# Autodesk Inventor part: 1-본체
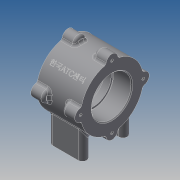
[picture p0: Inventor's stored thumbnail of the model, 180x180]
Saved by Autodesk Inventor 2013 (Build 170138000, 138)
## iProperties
Created: 2015-03
Part Number: 1-본체
Material: Generic
Document SubType Name: Modeling
Designer: kb
Density: 1 g/cm^3
Author: kb
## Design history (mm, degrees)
sketch "스케치1"
  geometry: L1 (-26, 37)-(26, 37); L2 (26, 37)-(26, 23.5); L3 (26, 23.5)-(4, 23.5); L4 (4, 23.5)-(4, 21); L5 (4, 21)-(-4, 21); L6 (-4, 21)-(-4, 23.5); L7 (-4, 23.5)-(-26, 23.5); L8 (-26, 23.5)-(-26, 37); L9 (-26, 0)-(26, 0); 2 further points
  constraints: 18 end point, 5 parallel, 3 perpendicular, 2 vertical alignment, 1 coincident, 1 horizontal, 1 midpoint
  dimensions: "d1" = 47 diameter of L7 L9; "d3" = 42 diameter of L5 L9; "d4" = 47 diameter of L3 L9; "d5" = 74 diameter of L1 L9; "d6" = 52 distance of L1.start L1.end; "d7" = 22 distance of L6.end L7.end; "d8" = 22 distance of L2.end L3.end
revolve "회전1" sketch "스케치1" stored, may be unused: angle "d9" = 90 deg
sketch "스케치2"
  geometry: L1 (0, 37)-(0, 0); C1 r 23.5 at (0, 0) reference; A1 r 37 centre (0, 0) between (0, 37) and (6.969, 36.338) reference; A2 r 7 centre (0, 37) between (6.969, 36.338) and (-6.969, 36.338); 1 further point
  constraints: 5 point on circle, 2 coincident, 2 end point, 1 centre point, 1 vertical
  dimensions: "d10" = 14 diameter of A2
extrude "돌출1" join sketch "스케치2" distance "d11" = 15; taper "d12" = 0 deg
hole "구멍1" sketch "스케치2" diameter "d13" = 3.242; stored, may be unused: countersink angle "d17" = 90 deg, drill point angle "d19" = 118 deg; dims "d14" = 8, "d15" = 4, "d16" = 2, "d18" = 11
node "작업 평면1"
node "작업 평면2"
sketch "스케치3"
  geometry: L1 (15, -24)-(-15, -24); L2 (-15, -24)-(-15, 24); L3 (-15, 24)-(15, 24); L4 (15, 24)-(15, -24); L5 (15, -24)-(-15, 24); L6 (-15, -24)-(15, 24); L7 (15, 29)-(-15, 29); L8 (15, 19)-(-15, 19); L9 (15, -19)-(-15, -19); L10 (15, -29)-(-15, -29); A1 r 5 centre (-15, 24) between (-15, 29) and (-15, 19); A2 r 5 centre (15, 24) between (15, 29) and (15, 19); A3 r 5 centre (-15, -24) between (-15, -19) and (-15, -29); A4 r 5 centre (15, -24) between (15, -19) and (15, -29); 1 further point
  constraints: 20 end point, 8 point on circle, 5 tangent, 4 centre point, 4 coincident, 3 point on line, 2 midpoint, 2 parallel, 1 horizontal, 1 perpendicular
  dimensions: "d24" = 48 distance of L3.end L1.start; "d26" = 30 distance of L2.end L3.end; "d27" = 10 diameter of A1; "d28" = 10 diameter of A2; "d29" = 10 diameter of A3; "d30" = 10 diameter of A4
extrude "돌출2" join sketch "스케치3" stored distance "d31" = 15; taper "d32" = 0 deg
sketch "스케치4"
  geometry: L1 (0, -37)-(-37, -37); L2 (0, -37)-(-48.443, -85.443); A1 r 37 centre (0, -37) between (-36.338, -43.969) and (-6.969, -73.338) reference; A2 r 37 centre (0, -37) between (36.338, -30.031) and (6.969, -0.662) reference; A3 r 37 centre (0, -37) between (-36.338, -30.031) and (-36.338, -43.969) reference; 1 further point
  constraints: 4 end point, 1 horizontal, 1 point on circle
  dimensions: "d33" = 45 deg angle of L1 L2
node "작업 평면3"
sketch "스케치5"
  geometry: L1 (-26, 20.767)-(-26, -20.767) reference; 3 further points
  constraints: 1 coincident, 1 other
  dimensions: "d34" = 26 distance from line of point (0, 0) L1
feature "엠보싱1" sketch "스케치5" dims "d15" = 4, "d35" = 0.5, "d36" = 0
sketch "스케치6"
  geometry: L1 (15, -29)-(-15, -29) reference; L2 (-15, -19)-(15, -19) reference; A1 r 5 centre (-15, 24) between (-15, 29) and (-15, 19) reference; A2 r 5 centre (15, 24) between (15, 19) and (15, 29) reference; A3 r 5 centre (-15, -24) between (-15, -19) and (-15, -29) reference; A4 r 5 centre (15, -24) between (15, -29) and (15, -19) reference; 5 further points
  constraints: 4 coincident
hole "구멍2" sketch "스케치6" at (-15, 24), (15, 24), (-15, -24), (15, -24) diameter "d37" = 4.134; stored, may be unused: countersink angle "d41" = 90 deg, drill point angle "d43" = 118 deg; dims "d38" = 6, "d39" = 4, "d40" = 2, "d42" = 8
fillet "모깎기1" dims "d44" = 3
fillet "모깎기2" dims "d45" = 3, "d46" = 0.3
chamfer "모따기1" distance "d47" = 1; stored, may be unused: second distance "d48" = 2, angle "d49" = 45 deg
node "솔리드1"
pattern_circular "원형 패턴1" dims angle "d21" = 360 deg
mirror "대칭1"
other parameters: "d23" = -56
